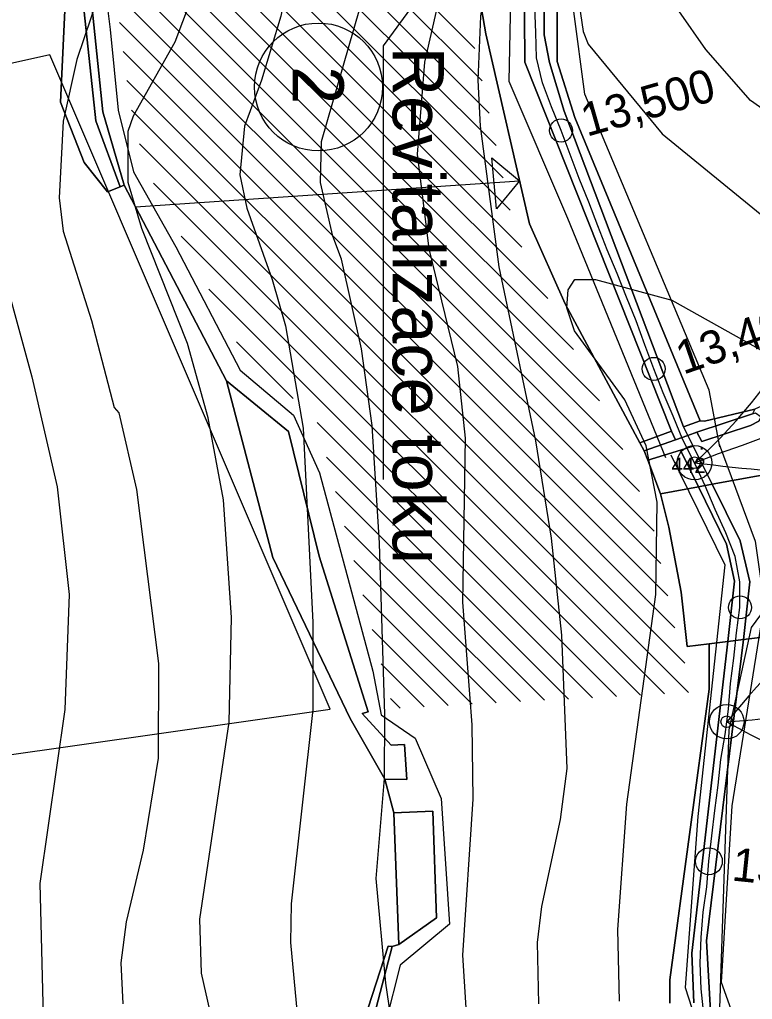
# Model space of a CAD drawing. Extents: x -510989 to -501240, y -1184665 to -1176089.
# Drawn here: x -510333.4 to -510047.2, y -1177955.3 to -1177572.4 of the extents above; entities that cross this region are included whole.
import ezdxf

# ---------------------------------------------------------------- set-up
doc = ezdxf.new("R2010")
doc.units = 0
for name, color, linetype in [('lesni_pozemek', 7, 'Continuous'), ('NAVRH_revitalizace_toku', 7, 'Continuous'), ('NAVRH_rozvodnice', 7, 'Continuous'), ('orna_puda', 7, 'Continuous'), ('ostatni_plocha_x_neplodna_puda', 7, 'Continuous'), ('ostatni_plocha_x_ostatni_komunikace', 7, 'Continuous'), ('STAV_erozne_ohrozene_plochy', 7, 'Continuous'), ('STAV_odtokove_linie', 7, 'Continuous'), ('STAV_systematicke_odvodneni', 7, 'Continuous'), ('STAV_USES', 7, 'Continuous'), ('trasovani_toku', 7, 'Continuous'), ('trvaly_travni_porost', 7, 'Continuous'), ('vodni_plocha_x_vodni_tok_v_koryte_umelem', 7, 'Continuous'), ('vrstevnice_01', 7, 'Continuous'), ('vrstevnice_02', 7, 'Continuous'), ('vrstevnice_05', 7, 'Continuous')]:
    doc.layers.add(name, color=color, linetype=linetype)

msp = doc.modelspace()

# ---------------------------------------------------------------- linework, layer by layer
at = {"layer": 'lesni_pozemek'}
msp.add_lwpolyline([(-510309.3, -1177366.43), (-510316.48, -1177386.96), (-510320.51, -1177402.61), (-510327.09, -1177444.96), (-510325.02, -1177489.16), (-510318.12, -1177532.77), (-510315.28, -1177560.29), (-510317.43, -1177604.64), (-510308.17, -1177628.21), (-510299, -1177639.71), (-510294.12, -1177637.73), (-510292.61, -1177637.11), (-510252.56, -1177713.54), (-510234.53, -1177782.61), (-510204.29, -1177845.51), (-510190.74, -1177869.24), (-510187.26, -1177882.35), (-510185.29, -1177933.82), (-510187.83, -1177934.64), (-510189.41, -1177934.52), (-510198.81, -1177963.46)], dxfattribs=at)
for points in [[(-510252.56, -1177713.54), (-510228.33, -1177733.41), (-510216.39, -1177782.07), (-510197.27, -1177842.86), (-510199.61, -1177843.6), (-510188.27, -1177856), (-510183.04, -1177855.68), (-510182.2, -1177869.41), (-510190.74, -1177869.24), (-510204.29, -1177845.51), (-510234.53, -1177782.61)], [(-510172.03, -1177881.72), (-510170.57, -1177923.47), (-510185.29, -1177933.82), (-510187.26, -1177882.35)], [(-510187.83, -1177934.64), (-510202.64, -1177991), (-510215.39, -1178019.77), (-510228.62, -1178044.97), (-510228.47, -1178052.46), (-510240.38, -1178070.99), (-510236.77, -1178049.95), (-510224.04, -1178022.91), (-510205.37, -1177988.67), (-510198.81, -1177963.46), (-510189.41, -1177934.52)]]:
    msp.add_lwpolyline(points, close=True, dxfattribs=at)
at = {"layer": 'NAVRH_revitalizace_toku'}
for points in [[(-510059.86, -1177739.28), (-510064.11, -1177717.17), (-510112.6, -1177601.48), (-510116.86, -1177569.15), (-510116, -1177448.36), (-510079.43, -1177415.19), (-510070.07, -1177380.31), (-510064.11, -1177346.29), (-510049.65, -1177288.44)], [(-510075.17, -1177292.7), (-510089.63, -1177359.05), (-510129.61, -1177414.34), (-510139.82, -1177439.86), (-510140.67, -1177513.01), (-510142.37, -1177596.38), (-510119.41, -1177649.97), (-510081.13, -1177743.53)], [(-510140.67, -1177513.01), (-510191.39, -1177582.56), (-510191.34, -1177752.07)], [(-510060.1, -1177738.31), (-510046.04, -1177776.27), (-510042.52, -1177800.88), (-510055.18, -1177879.61), (-510059.4, -1177948.51), (-510041.82, -1177997.72), (-510013.7, -1178078.56), (-509968.71, -1178171.36), (-509924.51, -1178222.53), (-509906.94, -1178282.99), (-509903.42, -1178334.31), (-509883.74, -1178387.03), (-509875.3, -1178456.63), (-509874.6, -1178556.46), (-509867.57, -1178669.64)], [(-510079.08, -1177742.53), (-510057.99, -1177785.41), (-510068.53, -1177883.83), (-510073.46, -1177950.62), (-510054.47, -1178009.67), (-510024.24, -1178091.92), (-509980.66, -1178181.91), (-509942.44, -1178221.73), (-509934.15, -1178235.7), (-509920.62, -1178289.39), (-509918.19, -1178331.5), (-509899.91, -1178389.14), (-509890.77, -1178450.3), (-509893.58, -1178526.93), (-509883.74, -1178663.31)]]:
    msp.add_lwpolyline(points, dxfattribs=at)
at = {"layer": 'NAVRH_rozvodnice'}
for centre, radius, start, end in [((-510207.31, -1177592.79), 205.55, 311.9981, 352.9555), ((-509946.05, -1176723.86), 1029.16, 263.0952, 269.69926), ((-509698.83, -1178144.4), 465.84, 122.8391, 140.2896), ((-509896.79, -1177561.03), 327.69, 240.6902, 256.011)]:
    msp.add_arc(centre, radius, start, end, dxfattribs=at)
at = {"layer": 'orna_puda'}
for points in [[(-509903.08, -1177271.99), (-509906.47, -1177405.26), (-509907.24, -1177447.42), (-509919.35, -1177521.3), (-509940.02, -1177559.56), (-509932.88, -1177599.21), (-509966.13, -1177637.97), (-509980.54, -1177661.84), (-509986.51, -1177693.69), (-510011.12, -1177708.83), (-510046.21, -1177724.59), (-510065.83, -1177729.25), (-510067.57, -1177729.21), (-510116.51, -1177610.57), (-510123.38, -1177588.75), (-510123.04, -1177446.95), (-510102.14, -1177427.79), (-510084.34, -1177409.75), (-510084.36, -1177388.11), (-510071.74, -1177384.51), (-510072, -1177373.55)], [(-510098.1, -1177374.8), (-510122.35, -1177392.2), (-510143.03, -1177412.76), (-510156.18, -1177433.8), (-510159.77, -1177529), (-510151.28, -1177577.98), (-510134.26, -1177652.15), (-510120.32, -1177683.49), (-510091.19, -1177737.71), (-510089.47, -1177740.92), (-510088.06, -1177744.6), (-510083.05, -1177757.65), (-510079.86, -1177770.71), (-510075.01, -1177796.11), (-510072.6, -1177817.38), (-510064.11, -1177816.33), (-510064.11, -1177834.11), (-510079.43, -1177947.66), (-510079.36, -1177956.75)], [(-510202.64, -1177991), (-510187.83, -1177934.64), (-510185.29, -1177933.82), (-510170.57, -1177923.47), (-510172.03, -1177881.72), (-510187.26, -1177882.35), (-510190.74, -1177869.24), (-510182.2, -1177869.41), (-510183.04, -1177855.68), (-510188.27, -1177856), (-510199.61, -1177843.6), (-510197.27, -1177842.86), (-510216.39, -1177782.07), (-510228.33, -1177733.41), (-510252.56, -1177713.54), (-510292.61, -1177637.11), (-510300.9, -1177608.36), (-510313.63, -1177484.87)], [(-510063.48, -1177959.85), (-510065.05, -1177932.43), (-510050.69, -1177814.67), (-510019.81, -1177810.86), (-510024.61, -1177784.41), (-510009.48, -1177781.92), (-509999.95, -1177832.76), (-509998.03, -1177877.57), (-509994.11, -1177899.83), (-509986.97, -1177924.63), (-509979.84, -1177959.29)]]:
    msp.add_lwpolyline(points, dxfattribs=at)
for points in [[(-510021.43, -1177723.87), (-510016.11, -1177731.56), (-510015.35, -1177750.63), (-510009.48, -1177781.92), (-510024.61, -1177784.41), (-510019.81, -1177810.86), (-510050.69, -1177814.67), (-510048.12, -1177792.11), (-510051.98, -1177776.06), (-510062.93, -1177753.96), (-510036.18, -1177749.06), (-510042.58, -1177731.02), (-510029.41, -1177725.92)], [(-510029.41, -1177725.92), (-510042.58, -1177731.02), (-510036.18, -1177749.06), (-510062.93, -1177753.96), (-510070.3, -1177739.1), (-510072.41, -1177734.85), (-510068.89, -1177733.6), (-510066.91, -1177737.27), (-510047.94, -1177731.06), (-510044.64, -1177729.31), (-510043.77, -1177727.66), (-510043.22, -1177729.19)], [(-510047.13, -1177726.45), (-510045.99, -1177726.07), (-510043.77, -1177727.66), (-510044.64, -1177729.31), (-510047.94, -1177731.06), (-510066.91, -1177737.27), (-510068.89, -1177733.6)]]:
    msp.add_lwpolyline(points, close=True, dxfattribs=at)
at = {"layer": 'ostatni_plocha_x_neplodna_puda'}
msp.add_lwpolyline([(-510327.09, -1177444.96), (-510320.51, -1177402.61), (-510320.38, -1177454.43), (-510315.9, -1177496.43), (-510308.93, -1177561.88), (-510303.6, -1177611.95), (-510294.12, -1177637.73), (-510299, -1177639.71), (-510308.17, -1177628.21), (-510317.43, -1177604.64), (-510315.28, -1177560.29), (-510318.12, -1177532.77), (-510325.02, -1177489.16)], close=True, dxfattribs=at)
at = {"layer": 'ostatni_plocha_x_ostatni_komunikace'}
for points in [[(-510082.36, -1177368.53), (-510128.78, -1177432.41), (-510128.56, -1177578.38), (-510126.42, -1177589.11), (-510120.67, -1177608.13), (-510074.05, -1177731.54), (-510072.41, -1177734.85), (-510077.22, -1177736.56), (-510078.83, -1177733.26), (-510136, -1177589.03), (-510137.13, -1177443.58), (-510125.71, -1177419.39), (-510083.15, -1177353.98)], [(-510079.88, -1177369.48), (-510123.01, -1177433.04), (-510123.04, -1177446.95), (-510123.38, -1177588.75), (-510116.51, -1177610.57), (-510067.57, -1177729.21), (-510074.05, -1177731.54), (-510120.67, -1177608.13), (-510126.42, -1177589.11), (-510128.56, -1177578.38), (-510128.78, -1177432.41), (-510082.36, -1177368.53)]]:
    msp.add_lwpolyline(points, dxfattribs=at)
msp.add_lwpolyline([(-510320.51, -1177402.61), (-510316.48, -1177386.96), (-510316.73, -1177421.27), (-510316.96, -1177453.2), (-510313.63, -1177484.87), (-510300.9, -1177608.36), (-510292.61, -1177637.11), (-510294.12, -1177637.73), (-510303.6, -1177611.95), (-510308.93, -1177561.88), (-510315.9, -1177496.43), (-510320.38, -1177454.43)], close=True, dxfattribs=at)
at = {"layer": 'STAV_erozne_ohrozene_plochy'}
for p, q in [((-510304.42, -1177494.12), (-510137.23, -1177661.31)), ((-510296.42, -1177492.22), (-510141.77, -1177646.86)), ((-510284.02, -1177494.72), (-510144.52, -1177634.21)), ((-510271.61, -1177497.23), (-510147.28, -1177621.56)), ((-510241.18, -1177497.96), (-510155.53, -1177583.61)), ((-510260.12, -1177498.82), (-510150.03, -1177608.91)), ((-510250.65, -1177498.39), (-510152.78, -1177596.26)), ((-510302.99, -1177505.45), (-510127.12, -1177681.32)), ((-510301.56, -1177516.78), (-510117.01, -1177701.33)), ((-510300.13, -1177528.11), (-510106.9, -1177721.34)), ((-510298.69, -1177539.44), (-510097.75, -1177740.39)), ((-510297.26, -1177550.77), (-510091.21, -1177756.83)), ((-510295.83, -1177562.1), (-510085.59, -1177772.34)), ((-510294.4, -1177573.44), (-510082.9, -1177784.93)), ((-510292.97, -1177584.77), (-510080.21, -1177797.52)), ((-510291.53, -1177596.1), (-510077.52, -1177810.11)), ((-510289.73, -1177607.8), (-510073.6, -1177823.93)), ((-510286.57, -1177620.86), (-510072.1, -1177835.33)), ((-510281.07, -1177636.26), (-510081.49, -1177835.85)), ((-510270.27, -1177656.96), (-510090.87, -1177836.36)), ((-510259.47, -1177677.66), (-510100.26, -1177836.87)), ((-510248.67, -1177698.36), (-510226.59, -1177720.44)), ((-510217.15, -1177729.88), (-510109.65, -1177837.38)), ((-510213.58, -1177743.35), (-510119.03, -1177837.9)), ((-510210.01, -1177756.82), (-510128.42, -1177838.41)), ((-510206.43, -1177770.29), (-510137.81, -1177838.92)), ((-510202.86, -1177783.77), (-510147.2, -1177839.43)), ((-510199.29, -1177797.24), (-510156.58, -1177839.94)), ((-510195.72, -1177810.71), (-510165.97, -1177840.46)), ((-510192.15, -1177824.18), (-510175.36, -1177840.97)), ((-510188.58, -1177837.65), (-510184.74, -1177841.48))]:
    msp.add_line(p, q, dxfattribs=at)
at = {"layer": 'STAV_odtokove_linie'}
msp.add_line((-510288.17, -1177645.58), (-510138.09, -1177635.44), dxfattribs=at)
msp.add_lwpolyline([(-510148.96, -1177626.4), (-510138.09, -1177635.44), (-510147.14, -1177646.31)], close=True, dxfattribs=at)
msp.add_circle((-510216.66, -1177598.7), 25, dxfattribs=at)
at = {"layer": 'STAV_systematicke_odvodneni'}
for p, q in [((-510302.85, -1177535.56), (-510298.04, -1177576.2)), ((-510298.04, -1177576.2), (-510294.83, -1177607.75)), ((-510294.83, -1177607.75), (-510288.95, -1177631.81)), ((-510288.95, -1177631.81), (-510272.38, -1177661.22)), ((-510272.38, -1177661.22), (-510247.26, -1177709.35)), ((-510247.26, -1177709.35), (-510226.41, -1177727)), ((-510226.41, -1177727), (-510216.26, -1177749.46)), ((-510216.26, -1177749.46), (-510195.41, -1177827)), ((-510195.41, -1177827), (-510192.2, -1177844.11)), ((-510192.2, -1177844.11), (-510178.84, -1177853.2)), ((-510178.84, -1177853.2), (-510168.68, -1177876.73)), ((-510168.68, -1177876.73), (-510165.48, -1177925.92)), ((-510165.48, -1177925.92), (-510184.72, -1177941.97)), ((-510184.72, -1177941.97), (-510196.48, -1177987.96))]:
    msp.add_line(p, q, dxfattribs=at)
at = {"layer": 'STAV_USES'}
for p, q in [((-510321.58, -1177586.16), (-510416.72, -1177607.14)), ((-510321.58, -1177586.16), (-510416.72, -1177607.14)), ((-510212.14, -1177841.84), (-510321.58, -1177586.16)), ((-510212.14, -1177841.84), (-510321.58, -1177586.16)), ((-510354.5, -1177862.11), (-510212.14, -1177841.84)), ((-510354.5, -1177862.11), (-510212.14, -1177841.84))]:
    msp.add_line(p, q, dxfattribs=at)
at = {"layer": 'trasovani_toku'}
for p, q in [((-510131.73, -1177577.34), (-510132.09, -1177567.35)), ((-510131.5, -1177587.34), (-510131.73, -1177577.34)), ((-510129.2, -1177597.07), (-510131.5, -1177587.34)), ((-510125.61, -1177606.4), (-510129.2, -1177597.07)), ((-510121.92, -1177615.7), (-510125.61, -1177606.4)), ((-510118.3, -1177625.02), (-510121.92, -1177615.7)), ((-510114.87, -1177634.41), (-510118.3, -1177625.02)), ((-510111.05, -1177643.65), (-510114.87, -1177634.41)), ((-510107.55, -1177653.02), (-510111.05, -1177643.65)), ((-510103.92, -1177662.34), (-510107.55, -1177653.02)), ((-510100.01, -1177671.54), (-510103.92, -1177662.34)), ((-510096.33, -1177680.84), (-510100.01, -1177671.54)), ((-510092.51, -1177690.08), (-510096.33, -1177680.84)), ((-510089.13, -1177699.49), (-510092.51, -1177690.08)), ((-510085.72, -1177708.89), (-510089.13, -1177699.49)), ((-510082.08, -1177718.21), (-510085.72, -1177708.89)), ((-510078.08, -1177727.37), (-510082.08, -1177718.21)), ((-510074.29, -1177736.62), (-510078.08, -1177727.37)), ((-510051.01, -1177738.63), (-510041.61, -1177735.23)), ((-510069.78, -1177745.55), (-510074.29, -1177736.62)), ((-510060.43, -1177741.99), (-510051.01, -1177738.63)), ((-510069.78, -1177745.55), (-510060.43, -1177741.99)), ((-510065.56, -1177754.62), (-510069.78, -1177745.55)), ((-510061.66, -1177763.82), (-510065.56, -1177754.62)), ((-510057.49, -1177772.91), (-510061.66, -1177763.82)), ((-510053.92, -1177782.25), (-510057.49, -1177772.91)), ((-510052.06, -1177792.08), (-510053.92, -1177782.25)), ((-510052.02, -1177802.08), (-510052.06, -1177792.08)), ((-510053.44, -1177811.98), (-510052.02, -1177802.08)), ((-510054.47, -1177821.93), (-510053.44, -1177811.98)), ((-510055.73, -1177831.85), (-510054.47, -1177821.93)), ((-510056.54, -1177841.81), (-510055.73, -1177831.85)), ((-510057.86, -1177851.73), (-510056.54, -1177841.81)), ((-510057.2, -1177846.77), (-510047.22, -1177846.07)), ((-510047.22, -1177846.07), (-510037.3, -1177844.81)), ((-510059.47, -1177861.6), (-510057.86, -1177851.73)), ((-510060.55, -1177871.54), (-510059.47, -1177861.6)), ((-510061.79, -1177881.46), (-510060.55, -1177871.54)), ((-510063.05, -1177891.38), (-510061.79, -1177881.46)), ((-510064.17, -1177901.32), (-510063.05, -1177891.38)), ((-510065.02, -1177911.28), (-510064.17, -1177901.32)), ((-510066.37, -1177921.19), (-510065.02, -1177911.28)), ((-510067.19, -1177931.16), (-510066.37, -1177921.19)), ((-510067.64, -1177941.15), (-510067.19, -1177931.16)), ((-510067.19, -1177951.14), (-510067.64, -1177941.15)), ((-510066.12, -1177961.08), (-510067.19, -1177951.14))]:
    msp.add_line(p, q, dxfattribs=at)
for centre, radius in [((-510121.92, -1177615.7), 4.5), ((-510085.72, -1177708.89), 4.5), ((-510069.78, -1177745.55), 6.75), ((-510069.78, -1177745.55), 2.25), ((-510052.02, -1177802.08), 4.5), ((-510057.2, -1177846.77), 6.75), ((-510057.2, -1177846.77), 2.25), ((-510064.17, -1177901.32), 5.25)]:
    msp.add_circle(centre, radius, dxfattribs=at)
at = {"layer": 'trvaly_travni_porost'}
for points in [[(-510082.63, -1177292.86), (-510070.28, -1177289.5), (-510083.15, -1177353.98), (-510125.71, -1177419.39), (-510137.13, -1177443.58), (-510136, -1177589.03), (-510078.83, -1177733.26), (-510091.19, -1177737.71), (-510120.32, -1177683.49), (-510134.26, -1177652.15), (-510151.28, -1177577.98), (-510159.77, -1177529), (-510156.18, -1177433.8), (-510143.03, -1177412.76), (-510122.35, -1177392.2), (-510098.1, -1177374.8), (-510093.86, -1177366.32), (-510095.14, -1177356.56), (-510093.39, -1177342.83)], [(-510077.22, -1177736.56), (-510089.47, -1177740.92), (-510091.19, -1177737.71), (-510078.83, -1177733.26)], [(-510072.41, -1177734.85), (-510070.3, -1177739.1), (-510075.24, -1177740.63), (-510088.06, -1177744.6), (-510089.47, -1177740.92), (-510077.22, -1177736.56)], [(-510088.06, -1177744.6), (-510075.24, -1177740.63), (-510068.26, -1177754.94), (-510083.05, -1177757.65)], [(-510068.26, -1177754.94), (-510057.29, -1177777.4), (-510054.18, -1177791.8), (-510056.77, -1177815.42), (-510064.11, -1177816.33), (-510072.6, -1177817.38), (-510075.01, -1177796.11), (-510079.86, -1177770.71), (-510083.05, -1177757.65)]]:
    msp.add_lwpolyline(points, close=True, dxfattribs=at)
msp.add_lwpolyline([(-510079.36, -1177956.75), (-510079.43, -1177947.66), (-510064.11, -1177834.11), (-510064.11, -1177816.33), (-510056.77, -1177815.42), (-510070.88, -1177937.17), (-510070.02, -1177956.7)], dxfattribs=at)
at = {"layer": 'vodni_plocha_x_vodni_tok_v_koryte_umelem'}
for points in [[(-510046.21, -1177724.59), (-510047.13, -1177726.45), (-510068.89, -1177733.6), (-510072.41, -1177734.85), (-510074.05, -1177731.54), (-510067.57, -1177729.21), (-510065.83, -1177729.25)], [(-510075.24, -1177740.63), (-510070.3, -1177739.1), (-510062.93, -1177753.96), (-510068.26, -1177754.94)], [(-510062.93, -1177753.96), (-510051.98, -1177776.06), (-510048.12, -1177792.11), (-510050.69, -1177814.67), (-510056.77, -1177815.42), (-510054.18, -1177791.8), (-510057.29, -1177777.4), (-510068.26, -1177754.94)]]:
    msp.add_lwpolyline(points, close=True, dxfattribs=at)
msp.add_lwpolyline([(-510070.02, -1177956.7), (-510070.88, -1177937.17), (-510056.77, -1177815.42), (-510050.69, -1177814.67), (-510065.05, -1177932.43), (-510063.48, -1177959.85)], dxfattribs=at)
at = {"layer": 'vrstevnice_01'}
for points in [[(-510266.31, -1177331), (-510305, -1177398), (-510315.91, -1177424), (-510322.81, -1177447), (-510322.59, -1177502), (-510323.81, -1177516), (-510331.59, -1177547), (-510337.09, -1177564), (-510345.69, -1177611), (-510346.41, -1177620), (-510343.69, -1177657), (-510328.59, -1177712), (-510318.69, -1177755), (-510314.09, -1177797), (-510315.69, -1177842), (-510325.5, -1177910), (-510323.5, -1177988)], [(-510253.09, -1177986), (-510262.41, -1177945), (-510263, -1177924), (-510251.59, -1177847), (-510250.69, -1177806), (-510253.69, -1177760), (-510259.69, -1177728), (-510267.81, -1177699), (-510285.69, -1177654), (-510291, -1177636), (-510291, -1177616), (-510288.91, -1177610), (-510272.69, -1177581), (-510263.31, -1177556), (-510258, -1177533), (-510257.5, -1177481), (-510252, -1177443), (-510241.31, -1177415), (-510225.31, -1177380), (-510201.91, -1177343)], [(-510182.59, -1178002), (-510190.31, -1177949), (-510194.09, -1177908), (-510190.91, -1177869), (-510190.69, -1177844), (-510192.81, -1177777), (-510195.69, -1177731), (-510199.81, -1177701), (-510207.69, -1177666), (-510211, -1177657), (-510215.91, -1177636), (-510215.5, -1177620), (-510200.5, -1177568), (-510198.91, -1177539), (-510199.81, -1177529), (-510195.91, -1177481), (-510188, -1177446), (-510177.81, -1177422), (-510162, -1177399)], [(-510130.59, -1177957), (-510131.09, -1177933), (-510129.41, -1177919), (-510122.09, -1177885), (-510119.5, -1177865), (-510121.59, -1177813), (-510125.59, -1177775), (-510131.81, -1177737), (-510146.09, -1177669), (-510153.41, -1177614), (-510154.31, -1177596), (-510153.19, -1177571), (-510147.19, -1177532), (-510146.59, -1177507), (-510143.59, -1177491), (-510137.81, -1177483), (-510130.19, -1177484), (-510125.5, -1177494), (-510113.31, -1177577), (-510111.31, -1177582), (-510082.41, -1177617), (-510042, -1177650)], [(-510006.91, -1177962), (-510013.31, -1177948), (-510018.91, -1177928), (-510017.09, -1177899), (-510013.59, -1177888), (-509998.31, -1177852), (-509999.5, -1177842), (-510018.19, -1177822), (-510036.69, -1177797), (-510038.19, -1177797), (-510047.69, -1177810), (-510056.41, -1177850), (-510060.81, -1177982)]]:
    msp.add_lwpolyline(points, dxfattribs=at)
at = {"layer": 'vrstevnice_02'}
for points in [[(-510254.69, -1177371), (-510262.41, -1177390), (-510287.91, -1177444), (-510291.19, -1177454), (-510293.19, -1177478), (-510293.09, -1177514), (-510294.91, -1177536), (-510297.19, -1177547), (-510311.09, -1177588), (-510316.41, -1177612), (-510318, -1177642), (-510316.41, -1177655), (-510305.31, -1177690), (-510296.41, -1177724), (-510294.59, -1177726), (-510287.69, -1177756), (-510279.09, -1177824), (-510279.31, -1177861), (-510285.09, -1177897), (-510291.81, -1177925), (-510293.81, -1177941), (-510293.09, -1177957)], [(-510174.91, -1177369), (-510196.81, -1177404), (-510214.09, -1177438), (-510222.69, -1177466), (-510225.09, -1177497), (-510225.09, -1177521), (-510227.5, -1177551), (-510231.41, -1177571), (-510238.91, -1177596), (-510245.5, -1177614), (-510247.41, -1177633), (-510244.69, -1177646), (-510234.69, -1177674), (-510229.59, -1177692), (-510222.69, -1177732), (-510218.81, -1177808), (-510218.91, -1177842), (-510227.31, -1177918), (-510227.59, -1177933), (-510225, -1177961)], [(-510168, -1177557), (-510175.31, -1177589), (-510178.09, -1177625), (-510173.5, -1177662), (-510162.31, -1177708), (-510159.41, -1177736), (-510160.41, -1177800), (-510156.81, -1177848), (-510156.41, -1177877), (-510160.41, -1177938), (-510158.31, -1177971)], [(-510042.19, -1177608), (-510047.91, -1177604), (-510065.31, -1177584), (-510075.91, -1177569)], [(-510099.09, -1177956), (-510099.69, -1177928), (-510096.19, -1177879), (-510084.91, -1177797), (-510084.31, -1177761), (-510088.69, -1177739), (-510097, -1177721), (-510116.69, -1177694), (-510119.69, -1177685), (-510119.19, -1177678), (-510116.59, -1177674), (-510108.5, -1177674), (-510078.69, -1177682), (-510039.31, -1177704)]]:
    msp.add_lwpolyline(points, dxfattribs=at)

# ---------------------------------------------------------------- texts
at = {"layer": 'NAVRH_revitalizace_toku'}
msp.add_text('Revitalizace toku', height=20, rotation=270, dxfattribs=at).set_placement((-510187.68, -1177582.96))
at = {"layer": 'STAV_odtokove_linie'}
msp.add_text('2', height=20, rotation=270, dxfattribs=at).set_placement((-510226.78, -1177590.55))
at = {"layer": 'trasovani_toku'}
for s, rotation, p in [('13,500', 15.7987, (-510111.89, -1177618.19)), ('13,400', 19.1411, (-510074.18, -1177711.19)), ('13,200', 354.066, (-510055.57, -1177908.79))]:
    msp.add_text(s, height=13, rotation=rotation, dxfattribs=at).set_placement(p)
at = {"layer": 'vrstevnice_05'}
for s, p in [('.', (-510068.08, -1177740.42)), ('442', (-510078.8, -1177749.58))]:
    msp.add_text(s, height=6, dxfattribs=at).set_placement(p)

doc.saveas('drawing.dxf')
